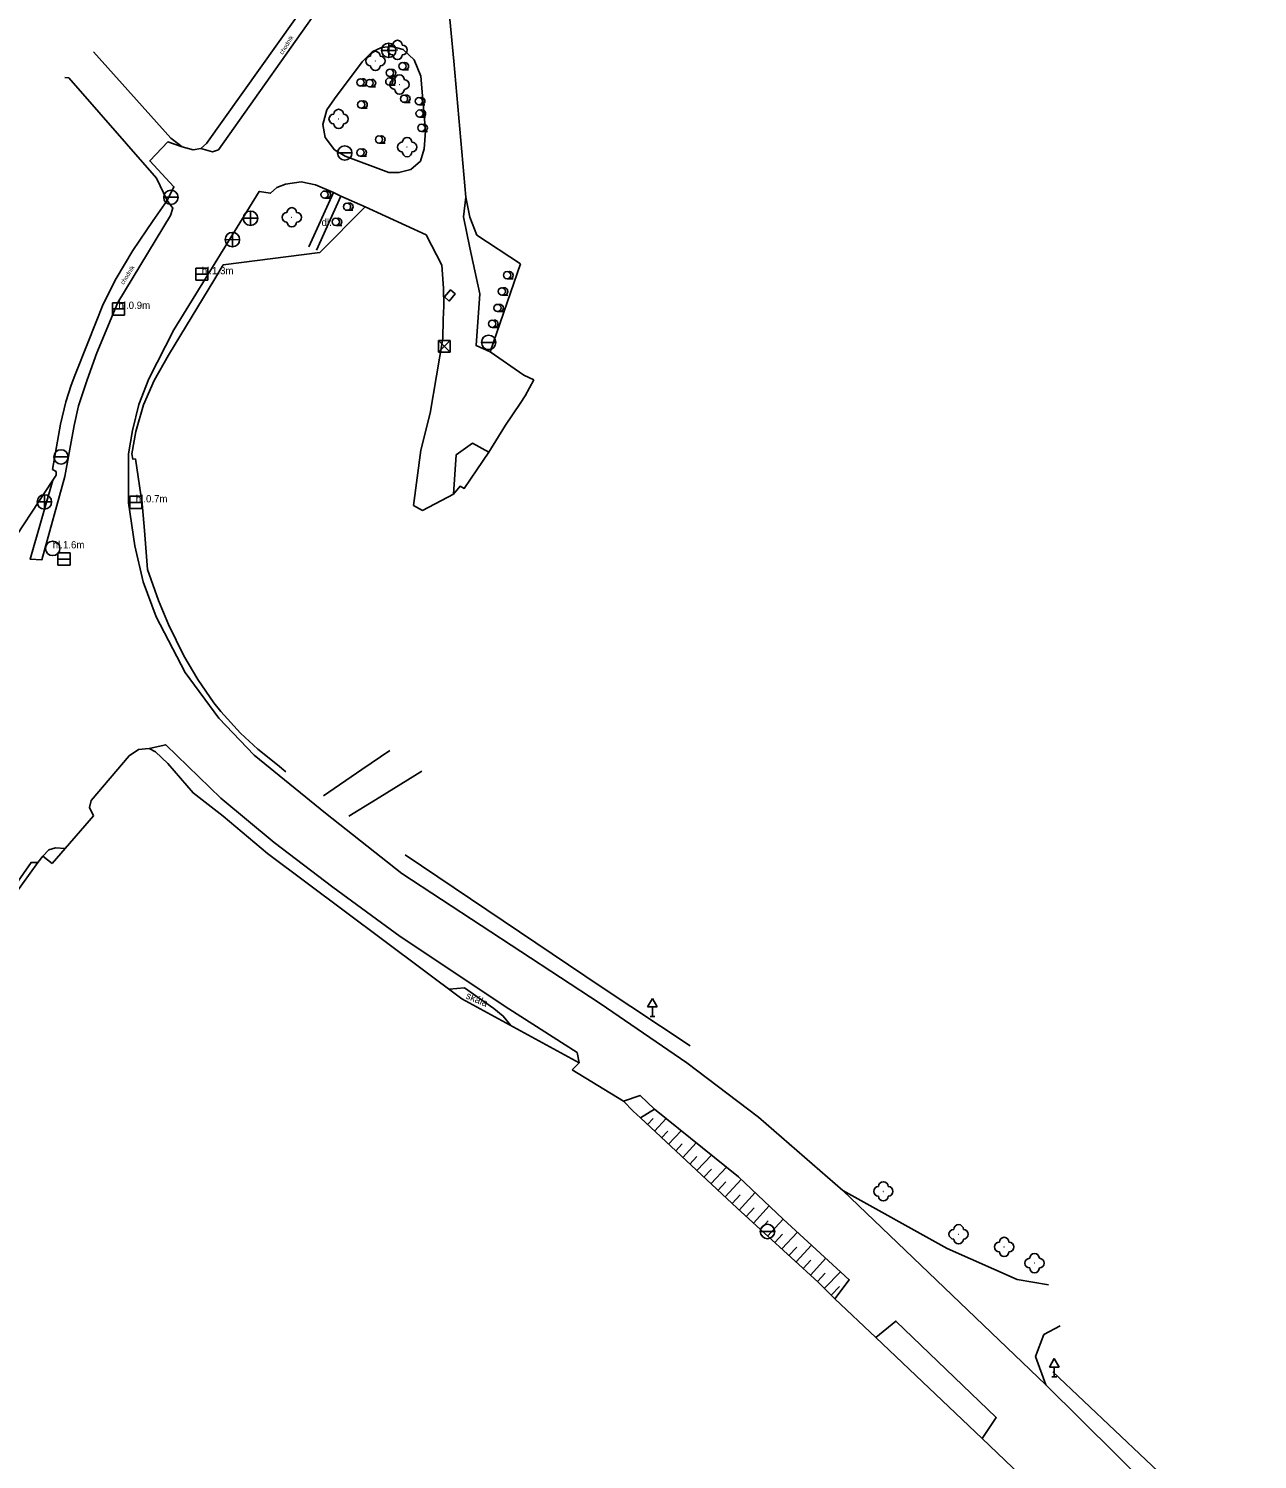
# Model space of a CAD drawing. Extents: x -747135 to -746147, y -1093269 to -1091735.
# Drawn here: x -746690.1 to -746562.6, y -1093185.8 to -1093037.4 of the extents above; entities that cross this region are included whole.
import ezdxf

# ---------------------------------------------------------------- set-up
doc = ezdxf.new("R2010")
doc.units = 0
for name, color, linetype in [('101', 7, 'Continuous'), ('1016', 7, 'Continuous'), ('1029', 7, 'Continuous'), ('105', 7, 'Continuous'), ('305', 7, 'Continuous'), ('306', 7, 'Continuous'), ('308', 7, 'Continuous'), ('316', 7, 'Continuous'), ('424', 7, 'Continuous'), ('803', 7, 'Continuous')]:
    doc.layers.add(name, color=color, linetype=linetype)

msp = doc.modelspace()

# ---------------------------------------------------------------- linework, layer by layer
at = {"layer": '101'}
for points in [[(-746606.39, -1093169.14), (-746604.9, -1093167.16), (-746611.75, -1093160.87), (-746616.39, -1093156.5), (-746625.13, -1093149.46), (-746626.61, -1093148.04), (-746628.35, -1093148.65)], [(-746625.13, -1093149.46), (-746626.57, -1093150.38)], [(-746625.84, -1093151.06), (-746625.26, -1093150.44)], [(-746625.11, -1093151.75), (-746623.9, -1093150.45)], [(-746624.38, -1093152.43), (-746623.75, -1093151.75)], [(-746623.65, -1093153.11), (-746622.34, -1093151.71)], [(-746622.92, -1093153.79), (-746622.24, -1093153.07)], [(-746622.19, -1093154.48), (-746620.78, -1093152.97)], [(-746621.45, -1093155.16), (-746620.72, -1093154.38)], [(-746620.72, -1093155.84), (-746619.21, -1093154.23)], [(-746619.26, -1093157.21), (-746617.65, -1093155.48)], [(-746619.99, -1093156.52), (-746619.21, -1093155.69)], [(-746617.8, -1093158.57), (-746616.11, -1093156.76)], [(-746618.53, -1093157.89), (-746617.7, -1093157)], [(-746617.07, -1093159.25), (-746616.23, -1093158.35)], [(-746616.34, -1093159.93), (-746614.68, -1093158.11)], [(-746615.6, -1093160.61), (-746614.77, -1093159.7)], [(-746614.86, -1093161.28), (-746613.22, -1093159.48)], [(-746614.12, -1093161.95), (-746613.31, -1093161.06)], [(-746613.38, -1093162.63), (-746611.77, -1093160.86)], [(-746612.64, -1093163.3), (-746611.83, -1093162.42)], [(-746611.9, -1093163.97), (-746610.29, -1093162.21)], [(-746611.16, -1093164.65), (-746610.36, -1093163.77)], [(-746610.42, -1093165.32), (-746608.82, -1093163.56)], [(-746609.68, -1093165.99), (-746608.88, -1093165.12)], [(-746608.94, -1093166.67), (-746607.35, -1093164.91)], [(-746608.2, -1093167.34), (-746607.41, -1093166.47)], [(-746607.49, -1093168.04), (-746605.8, -1093166.34)], [(-746606.78, -1093168.75), (-746605.92, -1093167.88)]]:
    msp.add_lwpolyline(points, dxfattribs=at)
at = {"layer": '1016'}
for points in [[(-746672.2, -1093049.79), (-746670.99, -1093050.13), (-746670.38, -1093049.94), (-746655.29, -1093028.58), (-746650.97, -1093022.36), (-746645.93, -1093015.13), (-746641.79, -1093008.8), (-746639.38, -1093004.9), (-746635.51, -1092997.79), (-746631.76, -1092990.25), (-746628.43, -1092982.94), (-746629.31, -1092981.37)], [(-746657.21, -1093050.59), (-746652.69, -1093052.29), (-746651.65, -1093052.29), (-746650.4, -1093051.99), (-746649.41, -1093051.1), (-746649.02, -1093049.84), (-746648.89, -1093047.99), (-746649.36, -1093042.29), (-746650.05, -1093040.58), (-746651.19, -1093039.52), (-746652.38, -1093039.21), (-746653.46, -1093039.32), (-746654.41, -1093039.76), (-746655.45, -1093040.79), (-746658.34, -1093044.64), (-746659.13, -1093045.8), (-746659.54, -1093047.31), (-746659.29, -1093048.65), (-746658.33, -1093049.93), (-746657.21, -1093050.59)], [(-746675.68, -1093055.2), (-746674.99, -1093053.77), (-746677.5, -1093051.08), (-746675.64, -1093049.11), (-746674.15, -1093049.62)], [(-746660.99, -1093060), (-746658.44, -1093054.36), (-746660.29, -1093053.55), (-746661.8, -1093053.25), (-746663.42, -1093053.5), (-746664.3, -1093053.85), (-746664.96, -1093054.44), (-746666.14, -1093054.24), (-746674.99, -1093068.6), (-746677.6, -1093073.69), (-746678.64, -1093076.35), (-746679.29, -1093079.05), (-746679.71, -1093081.48), (-746679.69, -1093086.54), (-746679.06, -1093091.02), (-746678.19, -1093094.74), (-746676.83, -1093098.38), (-746673.81, -1093104.16), (-746670.33, -1093108.89), (-746666.68, -1093112.75), (-746659.26, -1093118.75), (-746651.34, -1093125.01), (-746630.74, -1093138.49), (-746621.78, -1093144.65), (-746614.33, -1093150.3), (-746605.58, -1093157.9), (-746584.52, -1093178.06), (-746562.55, -1093199.83)], [(-746658.44, -1093054.36), (-746657.68, -1093054.73)], [(-746675.68, -1093055.2), (-746675.11, -1093056), (-746675.34, -1093056.75), (-746680.83, -1093065.77), (-746683.01, -1093071), (-746684.01, -1093073.81), (-746684.88, -1093076.49), (-746685.33, -1093078.52), (-746686.3, -1093083.83), (-746688.69, -1093092.46), (-746689.92, -1093092.39), (-746687.57, -1093084.22)], [(-746655.16, -1093055.86), (-746657.68, -1093054.73), (-746660.19, -1093060.33)], [(-746644.69, -1093054.86), (-746644.93, -1093056.89), (-746644.29, -1093060.11), (-746643.23, -1093064.87), (-746643.64, -1093070.24), (-746642.16, -1093070.89)], [(-746646.91, -1093065.19), (-746646.3, -1093064.46), (-746645.79, -1093064.89), (-746646.43, -1093065.62), (-746646.91, -1093065.19)], [(-746642.31, -1093081.3), (-746644.01, -1093080.38), (-746645.69, -1093081.56), (-746645.98, -1093085.67)], [(-746632.95, -1093144.66), (-746633.15, -1093143.59), (-746640.24, -1093139.06), (-746651.52, -1093131.54), (-746658.5, -1093126.44), (-746664.6, -1093121.81), (-746670.11, -1093117.2), (-746675.84, -1093111.66), (-746677.57, -1093112.05)], [(-746686.29, -1093122.43), (-746687.29, -1093122.36), (-746687.97, -1093122.56), (-746688.59, -1093123.22)], [(-746696.29, -1093140.24), (-746696.81, -1093140.08), (-746696.26, -1093138.64), (-746691.96, -1093126.95), (-746689.81, -1093123.87), (-746689.12, -1093123.88)], [(-746646.43, -1093137.03), (-746644.85, -1093136.89), (-746641.8, -1093139.03), (-746640.82, -1093139.81), (-746640.02, -1093140.78)], [(-746584.22, -1093167.7), (-746587.47, -1093167.14), (-746594.76, -1093163.92), (-746605.58, -1093157.9)], [(-746591.1, -1093183.64), (-746589.66, -1093181.47), (-746600.06, -1093171.45), (-746602.14, -1093173.16)], [(-746584.52, -1093178.06), (-746585.57, -1093175.11), (-746584.7, -1093172.86), (-746583.03, -1093171.96)]]:
    msp.add_lwpolyline(points, dxfattribs=at)
at = {"layer": '1029'}
for p, q in [((-746652.59, -1093042.32), (-746651.96, -1093042.32)), ((-746651.27, -1093041.64), (-746650.65, -1093041.64)), ((-746655.63, -1093043.31), (-746655.01, -1093043.31)), ((-746654.68, -1093043.39), (-746654.06, -1093043.39)), ((-746652.64, -1093043.23), (-746652.02, -1093043.23)), ((-746655.56, -1093045.61), (-746654.94, -1093045.61)), ((-746651.11, -1093045.01), (-746650.48, -1093045.01)), ((-746649.57, -1093045.26), (-746648.95, -1093045.26)), ((-746649.5, -1093046.54), (-746648.88, -1093046.54)), ((-746649.31, -1093048.02), (-746648.69, -1093048.02)), ((-746653.71, -1093049.24), (-746653.08, -1093049.24)), ((-746655.64, -1093050.59), (-746655.02, -1093050.59)), ((-746659.36, -1093054.96), (-746658.73, -1093054.96)), ((-746657.03, -1093056.21), (-746656.41, -1093056.21)), ((-746658.2, -1093057.77), (-746657.58, -1093057.77)), ((-746640.42, -1093063.31), (-746639.8, -1093063.31)), ((-746640.97, -1093065), (-746640.34, -1093065)), ((-746641.42, -1093066.72), (-746640.8, -1093066.72)), ((-746641.97, -1093068.35), (-746641.34, -1093068.35))]:
    msp.add_line(p, q, dxfattribs=at)
for centre in [(-746651.27, -1093041.26), (-746655.63, -1093042.94), (-746654.68, -1093043.01), (-746652.64, -1093042.85), (-746652.59, -1093041.95), (-746655.56, -1093045.24), (-746651.11, -1093044.63), (-746649.57, -1093044.88), (-746649.5, -1093046.17), (-746653.71, -1093048.86), (-746649.31, -1093047.65), (-746655.64, -1093050.22), (-746659.36, -1093054.58), (-746657.03, -1093055.83), (-746658.2, -1093057.4), (-746640.42, -1093062.94), (-746640.97, -1093064.62), (-746641.42, -1093066.34), (-746641.97, -1093067.98)]:
    msp.add_circle(centre, 0.375, dxfattribs=at)
for centre in [(-746651.02, -1093041.26), (-746655.38, -1093042.94), (-746654.43, -1093043.01), (-746652.39, -1093042.85), (-746652.34, -1093041.95), (-746655.31, -1093045.24), (-746650.86, -1093044.63), (-746649.32, -1093044.88), (-746649.25, -1093046.17), (-746653.46, -1093048.86), (-746649.06, -1093047.65), (-746655.39, -1093050.22), (-746659.11, -1093054.58), (-746656.78, -1093055.83), (-746657.95, -1093057.4), (-746640.17, -1093062.94), (-746640.72, -1093064.62), (-746641.17, -1093066.34), (-746641.72, -1093067.98)]:
    msp.add_arc(centre, 0.375, 249.4944, 109.0474, dxfattribs=at)
at = {"layer": '305'}
for points in [[(-746670.75, -1093063.3), (-746669.88, -1093061.86)], [(-746683.93, -1093069.96), (-746682.35, -1093065.96)], [(-746647.04, -1093067.52), (-746646.99, -1093066.16)], [(-746685.66, -1093074.34), (-746685.26, -1093073.36)], [(-746638.67, -1093073.3), (-746637.63, -1093073.78)], [(-746639.06, -1093076.24), (-746638.53, -1093075.44)], [(-746650.12, -1093086.83), (-746649.37, -1093081.09), (-746648.4, -1093077.24)], [(-746642.31, -1093081.3), (-746640.59, -1093078.5)], [(-746678.44, -1093085.74), (-746678.99, -1093081.99)], [(-746649.18, -1093087.34), (-746645.98, -1093085.67)], [(-746678.05, -1093089.42), (-746678.34, -1093086.25)], [(-746673.95, -1093102.43), (-746675.54, -1093099.19)], [(-746670.11, -1093108.19), (-746670.86, -1093107.31)], [(-746683.33, -1093119.04), (-746687.62, -1093123.97)], [(-746633.66, -1093145.39), (-746628.35, -1093148.65)], [(-746606.39, -1093169.14), (-746602.14, -1093173.16)], [(-746587.18, -1093187.4), (-746591.1, -1093183.64)]]:
    msp.add_lwpolyline(points, dxfattribs=at)
at = {"layer": '306'}
for p, q in [((-746625.33, -1093137.97), (-746625.83, -1093138.84)), ((-746625.83, -1093138.84), (-746624.83, -1093138.84)), ((-746625.33, -1093137.97), (-746624.83, -1093138.84)), ((-746625.33, -1093139.84), (-746625.33, -1093138.84)), ((-746625.58, -1093139.84), (-746625.08, -1093139.84)), ((-746583.63, -1093175.35), (-746584.13, -1093176.22)), ((-746584.13, -1093176.22), (-746583.13, -1093176.22)), ((-746583.63, -1093175.35), (-746583.13, -1093176.22)), ((-746583.63, -1093177.22), (-746583.63, -1093176.22)), ((-746583.88, -1093177.22), (-746583.38, -1093177.22))]:
    msp.add_line(p, q, dxfattribs=at)
at = {"layer": '308'}
for points in [[(-746675.55, -1093071.24), (-746670.75, -1093063.3)], [(-746692.77, -1093092.15), (-746687.57, -1093084.22), (-746687.22, -1093083.69), (-746687.2, -1093083.32), (-746687.58, -1093083.1)], [(-746665.29, -1093122.94), (-746645.12, -1093138.03)]]:
    msp.add_lwpolyline(points, dxfattribs=at)
at = {"layer": '316'}
for p, q in [((-746651.95, -1093039.62), (-746653.45, -1093039.61)), ((-746652.7, -1093040.36), (-746652.7, -1093038.86)), ((-746656.51, -1093050.26), (-746658.01, -1093050.26)), ((-746674.56, -1093054.86), (-746676.06, -1093054.86)), ((-746666.3, -1093057.04), (-746667.8, -1093057.03)), ((-746667.05, -1093057.78), (-746667.05, -1093056.28)), ((-746668.92, -1093060), (-746668.92, -1093058.5)), ((-746668.17, -1093059.26), (-746669.67, -1093059.25)), ((-746671.47, -1093062.21), (-746672.73, -1093062.21)), ((-746672.73, -1093062.21), (-746672.73, -1093063.47)), ((-746672.73, -1093062.84), (-746671.48, -1093062.84)), ((-746672.73, -1093063.47), (-746671.47, -1093063.47)), ((-746671.47, -1093063.47), (-746671.47, -1093062.21)), ((-746680.12, -1093065.81), (-746681.38, -1093065.81)), ((-746681.38, -1093065.81), (-746681.38, -1093067.07)), ((-746681.38, -1093066.44), (-746680.13, -1093066.44)), ((-746680.12, -1093067.07), (-746680.12, -1093065.81)), ((-746681.38, -1093067.07), (-746680.12, -1093067.07)), ((-746647.52, -1093069.73), (-746646.32, -1093070.93)), ((-746646.32, -1093069.73), (-746647.52, -1093070.93)), ((-746646.32, -1093069.73), (-746647.52, -1093069.73)), ((-746647.52, -1093069.73), (-746647.52, -1093070.93)), ((-746646.32, -1093070.93), (-746646.32, -1093069.73)), ((-746641.58, -1093069.91), (-746643.08, -1093069.91)), ((-746647.52, -1093070.93), (-746646.32, -1093070.93)), ((-746685.96, -1093081.79), (-746687.46, -1093081.79)), ((-746688.44, -1093087.21), (-746688.44, -1093085.71)), ((-746687.69, -1093086.47), (-746689.19, -1093086.46)), ((-746678.32, -1093085.88), (-746679.58, -1093085.88)), ((-746679.58, -1093085.88), (-746679.58, -1093087.14)), ((-746679.58, -1093086.51), (-746678.33, -1093086.51)), ((-746679.58, -1093087.14), (-746678.32, -1093087.14)), ((-746678.32, -1093087.14), (-746678.32, -1093085.88)), ((-746685.77, -1093091.76), (-746687.03, -1093091.76)), ((-746687.03, -1093091.76), (-746687.03, -1093093.02)), ((-746687.03, -1093092.39), (-746685.78, -1093092.39)), ((-746687.03, -1093093.02), (-746685.77, -1093093.02)), ((-746685.77, -1093093.02), (-746685.77, -1093091.76)), ((-746612.64, -1093162.16), (-746614.14, -1093162.16))]:
    msp.add_line(p, q, dxfattribs=at)
for centre in [(-746652.7, -1093039.61), (-746667.05, -1093057.03), (-746668.92, -1093059.25), (-746688.44, -1093086.46), (-746687.57, -1093091.28)]:
    msp.add_circle(centre, 0.75, dxfattribs=at)
for centre, start, end in [((-746657.26, -1093050.26), 0, 180), ((-746657.26, -1093050.26), 180, 0), ((-746675.31, -1093054.86), 0, 180), ((-746675.31, -1093054.86), 180, 0), ((-746642.33, -1093069.91), 0, 180), ((-746642.33, -1093069.91), 180, 0), ((-746686.71, -1093081.79), 0, 180), ((-746686.71, -1093081.79), 180, 0), ((-746613.39, -1093162.16), 0, 180), ((-746613.39, -1093162.16), 180, 0)]:
    msp.add_arc(centre, 0.747, start, end, dxfattribs=at)
at = {"layer": '424'}
for centre in [(-746651.79, -1093039.57), (-746654.08, -1093040.71), (-746651.58, -1093043.16), (-746657.9, -1093046.73), (-746650.79, -1093049.65), (-746662.76, -1093056.93), (-746601.37, -1093157.99), (-746593.56, -1093162.44), (-746588.83, -1093163.76), (-746585.68, -1093165.44)]:
    msp.add_circle(centre, 0.0005, dxfattribs=at)
for centre, start, end in [((-746654.08, -1093040.21), 0, 180), ((-746652.29, -1093039.57), 90, 270), ((-746651.79, -1093039.07), 0, 180), ((-746651.29, -1093039.57), 270, 90), ((-746654.58, -1093040.71), 90, 270), ((-746654.08, -1093041.21), 180, 360), ((-746653.58, -1093040.71), 270, 90), ((-746651.79, -1093040.07), 180, 360), ((-746652.08, -1093043.16), 90, 270), ((-746651.58, -1093042.66), 0, 180), ((-746651.08, -1093043.16), 270, 90), ((-746651.58, -1093043.66), 180, 360), ((-746658.4, -1093046.73), 90, 270), ((-746657.9, -1093046.23), 0, 180), ((-746657.4, -1093046.73), 270, 90), ((-746657.9, -1093047.23), 180, 360), ((-746651.29, -1093049.65), 90, 270), ((-746650.79, -1093049.15), 0, 180), ((-746650.29, -1093049.65), 270, 90), ((-746650.79, -1093050.15), 180, 360), ((-746662.76, -1093056.43), 0, 180), ((-746663.26, -1093056.93), 90, 270), ((-746662.76, -1093057.43), 180, 360), ((-746662.26, -1093056.93), 270, 90), ((-746601.37, -1093157.49), 0, 180), ((-746601.87, -1093157.99), 90, 270), ((-746600.87, -1093157.99), 270, 90), ((-746601.37, -1093158.49), 180, 360), ((-746593.56, -1093161.94), 0, 180), ((-746594.06, -1093162.44), 90, 270), ((-746593.06, -1093162.44), 270, 90), ((-746588.83, -1093163.26), 0, 180), ((-746593.56, -1093162.94), 180, 360), ((-746589.33, -1093163.76), 90, 270), ((-746588.83, -1093164.26), 180, 360), ((-746588.33, -1093163.76), 270, 90), ((-746586.18, -1093165.44), 90, 270), ((-746585.68, -1093164.94), 0, 180), ((-746585.18, -1093165.44), 270, 90), ((-746585.68, -1093165.94), 180, 360)]:
    msp.add_arc(centre, 0.5, start, end, dxfattribs=at)
at = {"layer": '803'}
for points in [[(-746683.34, -1093039.76), (-746675.31, -1093048.73), (-746674.15, -1093049.62), (-746673, -1093049.94), (-746672.2, -1093049.79), (-746671.6, -1093049.27), (-746658.67, -1093031.07)], [(-746644.69, -1093054.86), (-746645.95, -1093040.73), (-746646.37, -1093036.39), (-746646.19, -1093035.94), (-746644.02, -1093032.02)], [(-746676.81, -1093052.89), (-746685.91, -1093042.46), (-746686.31, -1093042.44)], [(-746682.35, -1093065.96), (-746680.97, -1093063.29), (-746679.26, -1093060.38), (-746677.15, -1093057.26), (-746675.68, -1093055.2), (-746676.81, -1093052.89)], [(-746646.99, -1093066.16), (-746647, -1093064.29), (-746647.19, -1093061.9), (-746648.83, -1093058.75), (-746655.16, -1093055.86), (-746659.85, -1093060.58)], [(-746644.69, -1093054.86), (-746644.27, -1093056.93), (-746643.56, -1093058.78), (-746639.04, -1093061.75)], [(-746659.85, -1093060.58), (-746669.88, -1093061.86)], [(-746639.04, -1093061.75), (-746642.16, -1093070.89), (-746638.67, -1093073.3)], [(-746648.4, -1093077.24), (-746647.07, -1093069.51), (-746647.04, -1093067.52)], [(-746685.26, -1093073.36), (-746683.93, -1093069.96)], [(-746678.99, -1093081.99), (-746679.25, -1093082.04), (-746679.37, -1093081.47), (-746678.95, -1093079.16), (-746678.16, -1093076.39), (-746677.05, -1093073.87), (-746675.55, -1093071.24)], [(-746637.63, -1093073.78), (-746638.53, -1093075.44)], [(-746687.58, -1093083.1), (-746686.77, -1093078.39), (-746686.2, -1093076.08), (-746685.66, -1093074.34)], [(-746639.06, -1093076.24), (-746640.59, -1093078.5)], [(-746642.31, -1093081.3), (-746643.56, -1093083.14)], [(-746643.56, -1093083.14), (-746644.86, -1093085.07), (-746645.29, -1093084.84), (-746645.98, -1093085.67)], [(-746678.34, -1093086.25), (-746678.44, -1093085.74)], [(-746649.18, -1093087.34), (-746650.12, -1093086.83)], [(-746675.54, -1093099.19), (-746676.58, -1093096.7), (-746677.73, -1093093.48), (-746678.05, -1093089.42)], [(-746670.86, -1093107.31), (-746672.52, -1093104.9), (-746673.95, -1093102.43)], [(-746664.26, -1093113.75), (-746666.3, -1093112.11), (-746668.1, -1093110.45), (-746670.11, -1093108.19)], [(-746683.33, -1093119.04), (-746683.77, -1093118.17), (-746683.59, -1093117.43), (-746679.64, -1093112.8), (-746678.66, -1093112.14), (-746677.57, -1093112.05), (-746676.92, -1093112.4), (-746675.62, -1093113.59), (-746673, -1093116.66), (-746669.88, -1093119.08), (-746665.29, -1093122.94)], [(-746659.46, -1093116.94), (-746655.49, -1093114.24), (-746652.59, -1093112.26)], [(-746663.38, -1093114.46), (-746664.26, -1093113.75)], [(-746656.84, -1093119.08), (-746653.61, -1093117.09), (-746649.26, -1093114.41)], [(-746687.62, -1093123.97), (-746688.59, -1093123.22), (-746689.12, -1093123.88), (-746691.49, -1093127.2), (-746695.73, -1093138.79), (-746697.94, -1093144.55)], [(-746621.41, -1093142.89), (-746630.66, -1093136.76), (-746650.99, -1093123.07)], [(-746645.12, -1093138.03), (-746632.95, -1093144.66), (-746633.66, -1093145.39)], [(-746628.35, -1093148.65), (-746627.34, -1093149.67)], [(-746627.34, -1093149.67), (-746626.57, -1093150.38), (-746616.54, -1093159.75), (-746608.14, -1093167.4), (-746606.39, -1093169.14)], [(-746602.14, -1093173.16), (-746591.1, -1093183.64)], [(-746567.68, -1093191.92), (-746583.79, -1093176.73)]]:
    msp.add_lwpolyline(points, dxfattribs=at)

# ---------------------------------------------------------------- texts
at = {"layer": '105'}
for s, height, rotation, p in [('chodník', 0.45, 57.6561, (-746663.71, -1093040.09)), ('dl.', 0.75, 0.3212, (-746659.67, -1093057.83)), ('chodník', 0.45, 57.6561, (-746680.21, -1093063.96)), ('skála', 0.75, 336.8014, (-746644.76, -1093137.95))]:
    msp.add_text(s, height=height, rotation=rotation, dxfattribs=at).set_placement(p)
for s, p in [('hl.1.3m', (-746672.1, -1093062.84)), ('hl.0.9m', (-746680.75, -1093066.44)), ('hl.0.7m', (-746678.95, -1093086.51)), ('hl.1.6m', (-746687.57, -1093091.28))]:
    msp.add_text(s, height=0.75, dxfattribs=at).set_placement(p)

doc.saveas('drawing.dxf')
